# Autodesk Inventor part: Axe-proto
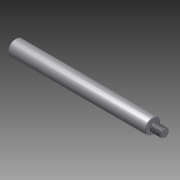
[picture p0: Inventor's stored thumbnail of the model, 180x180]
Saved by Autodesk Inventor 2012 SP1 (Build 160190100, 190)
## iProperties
Created: 2012-06
Part Number: Axe-proto
Material: Default
Document SubType Name: Modeling
Designer: Bruno
Density: 1 g/cm^3
Author: Bruno
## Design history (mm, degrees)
sketch "Esquisse1"
  geometry: L1 (80.033, 4.305)-(80.033, 1); L2 (81.033, 1.805)-(81.033, -0.038); L3 (80.033, -0.038)-(81.033, -0.038); L4 (-48.474, -2.195)-(91.078, -2.195); L5 (-48.474, 3.805)-(-47.474, 4.805); L6 (-48.474, -2.195)-(-48.474, 3.805); L7 (-47.474, 4.805)-(79.533, 4.805); L8 (80.033, 1)-(80.033, -0.038); L9 (81.033, 1.805)-(90.578, 1.805); L10 (91.078, 1.305)-(91.078, -2.195); L11 (91.078, 1.305)-(90.578, 1.805); L12 (80.033, 4.305)-(79.533, 4.805); 2 further points
  constraints: 24 end point, 6 perpendicular, 4 point on line
  dimensions: "d31" = 0.5 distance of L10.start point (91.078, 1.805); "d32" = 0.5 distance of L9.end point (91.078, 1.805) (= d31); "d40" = 7 distance between parallel lines of L7 L4; "d43" = 4 distance between parallel lines of L4 L9; "d46" = 1 horizontal distance of L5.end L5.start; "d47" = 1 horizontal distance of L5.end L5.start; "d48" = 0.5 distance of L1.start point (80.033, 4.805); "d49" = 0.5 distance of L7.end point (80.033, 4.805) (= d48)
revolve "Révolution1" sketch "Esquisse1" stored, may be unused: angle "d7" = 90 deg
feature "Filetage3" dims "d44" = 10, "d45" = 0
node "Solide1"
